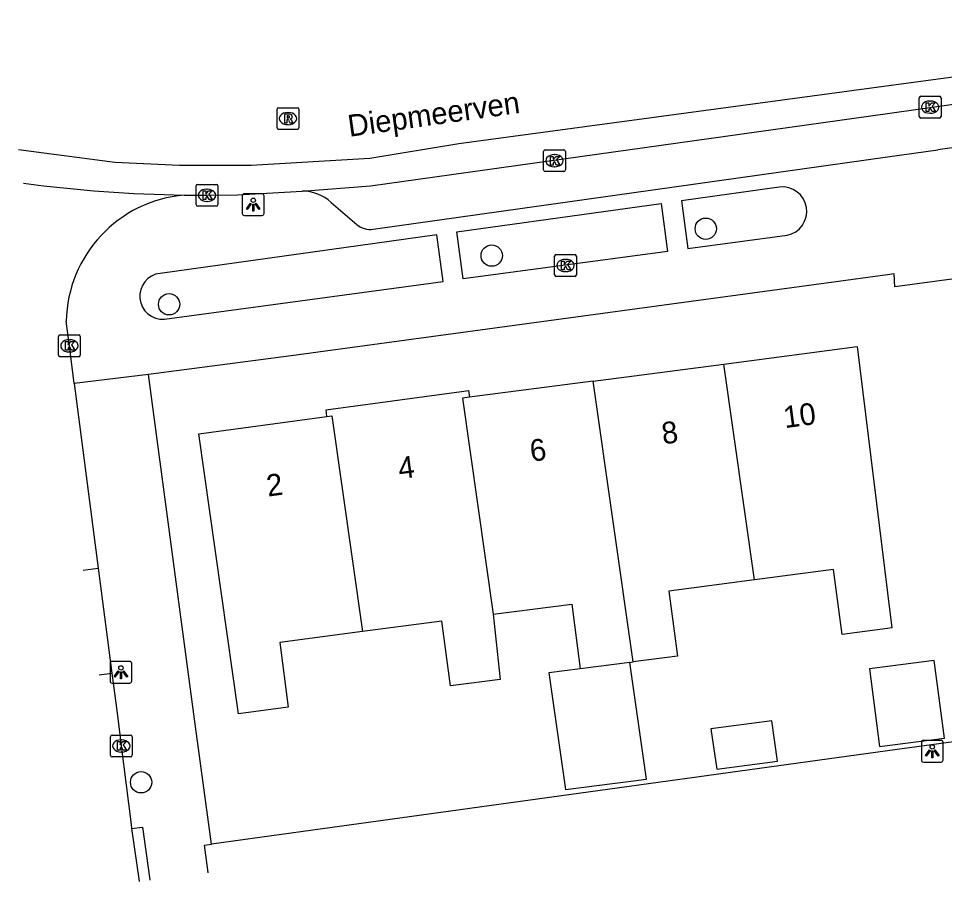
# Model space of a CAD drawing. Extents: x 163427 to 164190, y 380331 to 381641.
# Drawn here: x 163460.1 to 163502.62, y 381492.5 to 381532.13 of the extents above; entities that cross this region are included whole.
import ezdxf

# ---------------------------------------------------------------- set-up
doc = ezdxf.new("R2010")
doc.units = 0
for name, color, linetype in [('IMGEO_Boom', 7, 'Continuous'), ('IMGEO_Kolk', 7, 'Continuous'), ('IMGEO_Lichtpunt', 7, 'Continuous'), ('IMGEO_Openbare_ruimte_label', 7, 'Continuous'), ('IMGEO_Pand', 7, 'Continuous'), ('IMGEO_Pand_nummerreeks', 7, 'Continuous'), ('IMGEO_Rijbaan_lokaal_gesloten', 7, 'Continuous'), ('IMGEO_Rijbaan_lokaal_open', 7, 'Continuous'), ('IMGEO_Rioolput', 7, 'Continuous'), ('IMGEO_Voetpad_open', 7, 'Continuous')]:
    doc.layers.add(name, color=color, linetype=linetype)

msp = doc.modelspace()

# ---------------------------------------------------------------- linework, layer by layer
at = {"layer": 'IMGEO_Boom'}
for centre in [(163491.659, 381522.474), (163481.832, 381521.243), (163467.018, 381519.006), (163465.734, 381497.058)]:
    msp.add_circle(centre, 0.489, dxfattribs=at)
at = {"layer": 'IMGEO_Kolk'}
for p, q in [((163501.46, 381527.633), (163501.46, 381528.485)), ((163501.535, 381528.559), (163502.387, 381528.559)), ((163501.948, 381528.339), (163501.973, 381528.339)), ((163502.461, 381528.485), (163502.461, 381527.633)), ((163501.971, 381527.779), (163501.946, 381527.779)), ((163502.387, 381527.559), (163501.535, 381527.559)), ((163484.288, 381526.099), (163485.14, 381526.099)), ((163484.213, 381525.173), (163484.213, 381526.025)), ((163484.701, 381525.879), (163484.726, 381525.879)), ((163485.214, 381526.025), (163485.214, 381525.173)), ((163484.724, 381525.319), (163484.699, 381525.319)), ((163485.14, 381525.099), (163484.288, 381525.099)), ((163468.257, 381523.586), (163468.257, 381524.438)), ((163468.332, 381524.512), (163469.184, 381524.512)), ((163469.258, 381524.438), (163469.258, 381523.586)), ((163468.745, 381524.292), (163468.77, 381524.292)), ((163468.768, 381523.732), (163468.743, 381523.732)), ((163469.184, 381523.512), (163468.332, 381523.512)), ((163484.72, 381520.36), (163484.72, 381521.212)), ((163484.795, 381521.286), (163485.647, 381521.286)), ((163485.208, 381521.066), (163485.233, 381521.066)), ((163485.721, 381521.212), (163485.721, 381520.36)), ((163485.647, 381520.286), (163484.795, 381520.286)), ((163485.231, 381520.506), (163485.206, 381520.506)), ((163462.014, 381517.6), (163462.866, 381517.6)), ((163461.939, 381516.674), (163461.939, 381517.526)), ((163462.427, 381517.38), (163462.452, 381517.38)), ((163462.94, 381517.526), (163462.94, 381516.674)), ((163462.45, 381516.82), (163462.425, 381516.82)), ((163462.866, 381516.6), (163462.014, 381516.6)), ((163464.322, 381498.301), (163464.322, 381499.153)), ((163464.397, 381499.227), (163465.249, 381499.227)), ((163464.81, 381499.007), (163464.835, 381499.007)), ((163465.323, 381499.153), (163465.323, 381498.301)), ((163464.833, 381498.447), (163464.808, 381498.447)), ((163465.249, 381498.227), (163464.397, 381498.227))]:
    msp.add_line(p, q, dxfattribs=at)
for points in [[(163501.46, 381527.633), (163501.46, 381528.485)], [(163501.535, 381528.559), (163502.387, 381528.559)], [(163501.781, 381528.259), (163501.904, 381528.259), (163501.904, 381528.108), (163502.034, 381528.259), (163502.198, 381528.259), (163502.052, 381528.108), (163502.205, 381527.859), (163502.053, 381527.859), (163501.968, 381528.023), (163501.904, 381527.956), (163501.904, 381527.859), (163501.781, 381527.859), (163501.781, 381528.259)], [(163502.461, 381528.485), (163502.461, 381527.633)], [(163502.387, 381527.559), (163501.535, 381527.559)], [(163484.288, 381526.099), (163485.14, 381526.099)], [(163484.213, 381525.173), (163484.213, 381526.025)], [(163484.534, 381525.799), (163484.657, 381525.799), (163484.657, 381525.648), (163484.787, 381525.799), (163484.951, 381525.799), (163484.805, 381525.648), (163484.958, 381525.399), (163484.806, 381525.399), (163484.721, 381525.563), (163484.657, 381525.496), (163484.657, 381525.399), (163484.534, 381525.399), (163484.534, 381525.799)], [(163485.214, 381526.025), (163485.214, 381525.173)], [(163485.14, 381525.099), (163484.288, 381525.099)], [(163468.257, 381523.586), (163468.257, 381524.438)], [(163468.332, 381524.512), (163469.184, 381524.512)], [(163469.258, 381524.438), (163469.258, 381523.586)], [(163468.578, 381524.212), (163468.701, 381524.212), (163468.701, 381524.061), (163468.831, 381524.212), (163468.995, 381524.212), (163468.849, 381524.061), (163469.002, 381523.812), (163468.85, 381523.812), (163468.765, 381523.976), (163468.701, 381523.909), (163468.701, 381523.812), (163468.578, 381523.812), (163468.578, 381524.212)], [(163469.184, 381523.512), (163468.332, 381523.512)], [(163484.72, 381520.36), (163484.72, 381521.212)], [(163484.795, 381521.286), (163485.647, 381521.286)], [(163485.041, 381520.986), (163485.164, 381520.986), (163485.164, 381520.835), (163485.294, 381520.986), (163485.458, 381520.986), (163485.312, 381520.835), (163485.465, 381520.586), (163485.313, 381520.586), (163485.228, 381520.75), (163485.164, 381520.683), (163485.164, 381520.586), (163485.041, 381520.586), (163485.041, 381520.986)], [(163485.721, 381521.212), (163485.721, 381520.36)], [(163485.647, 381520.286), (163484.795, 381520.286)], [(163462.014, 381517.6), (163462.866, 381517.6)], [(163461.939, 381516.674), (163461.939, 381517.526)], [(163462.26, 381517.3), (163462.383, 381517.3), (163462.383, 381517.149), (163462.513, 381517.3), (163462.677, 381517.3), (163462.531, 381517.149), (163462.684, 381516.9), (163462.532, 381516.9), (163462.447, 381517.064), (163462.383, 381516.997), (163462.383, 381516.9), (163462.26, 381516.9), (163462.26, 381517.3)], [(163462.94, 381517.526), (163462.94, 381516.674)], [(163462.866, 381516.6), (163462.014, 381516.6)], [(163464.322, 381498.301), (163464.322, 381499.153)], [(163464.397, 381499.227), (163465.249, 381499.227)], [(163464.643, 381498.927), (163464.766, 381498.927), (163464.766, 381498.776), (163464.896, 381498.927), (163465.06, 381498.927), (163464.914, 381498.776), (163465.067, 381498.527), (163464.915, 381498.527), (163464.83, 381498.691), (163464.766, 381498.624), (163464.766, 381498.527), (163464.643, 381498.527), (163464.643, 381498.927)], [(163465.323, 381499.153), (163465.323, 381498.301)], [(163465.249, 381498.227), (163464.397, 381498.227)]]:
    msp.add_lwpolyline(points, dxfattribs=at)
for centre, start, end in [((163501.537, 381528.483), 91.552, 178.448), ((163501.537, 381528.483), 91.552, 178.448), ((163502.385, 381528.483), 1.552, 88.448), ((163502.385, 381528.483), 1.552, 88.448), ((163501.537, 381527.635), 181.552, 268.448), ((163501.537, 381527.635), 181.552, 268.448), ((163502.385, 381527.635), 271.552, 358.448), ((163502.385, 381527.635), 271.552, 358.448), ((163484.29, 381526.023), 91.552, 178.448), ((163484.29, 381526.023), 91.552, 178.448), ((163485.138, 381526.023), 1.552, 88.448), ((163485.138, 381526.023), 1.552, 88.448), ((163484.29, 381525.175), 181.552, 268.448), ((163484.29, 381525.175), 181.552, 268.448), ((163485.138, 381525.175), 271.552, 358.448), ((163485.138, 381525.175), 271.552, 358.448), ((163468.334, 381524.436), 91.552, 178.448), ((163468.334, 381524.436), 91.552, 178.448), ((163469.182, 381524.436), 1.552, 88.448), ((163469.182, 381524.436), 1.552, 88.448), ((163468.334, 381523.588), 181.552, 268.448), ((163468.334, 381523.588), 181.552, 268.448), ((163469.182, 381523.588), 271.552, 358.448), ((163469.182, 381523.588), 271.552, 358.448), ((163484.797, 381521.21), 91.552, 178.448), ((163484.797, 381521.21), 91.552, 178.448), ((163485.645, 381521.21), 1.552, 88.448), ((163485.645, 381521.21), 1.552, 88.448), ((163484.797, 381520.362), 181.552, 268.448), ((163484.797, 381520.362), 181.552, 268.448), ((163485.645, 381520.362), 271.552, 358.448), ((163485.645, 381520.362), 271.552, 358.448), ((163462.016, 381517.524), 91.552, 178.448), ((163462.016, 381517.524), 91.552, 178.448), ((163462.864, 381517.524), 1.552, 88.448), ((163462.864, 381517.524), 1.552, 88.448), ((163462.016, 381516.676), 181.552, 268.448), ((163462.016, 381516.676), 181.552, 268.448), ((163462.864, 381516.676), 271.552, 358.448), ((163462.864, 381516.676), 271.552, 358.448), ((163464.399, 381499.151), 91.552, 178.448), ((163464.399, 381499.151), 91.552, 178.448), ((163465.247, 381499.151), 1.552, 88.448), ((163465.247, 381499.151), 1.552, 88.448), ((163464.399, 381498.303), 181.552, 268.448), ((163464.399, 381498.303), 181.552, 268.448), ((163465.247, 381498.303), 271.552, 358.448), ((163465.247, 381498.303), 271.552, 358.448)]:
    msp.add_arc(centre, 0.0765, start, end, dxfattribs=at)
for centre, major_axis, ratio, start_param, end_param in [((163501.947, 381528.059), (-0.387, 0.002), 0.722429, 4.712389, 7.853982), ((163501.972, 381528.059), (-0.39, 0.002), 0.717154, 1.570796, 4.712389), ((163484.7, 381525.599), (-0.387, 0.002), 0.722429, 4.712389, 7.853982), ((163484.725, 381525.599), (-0.39, 0.002), 0.717154, 1.570796, 4.712389), ((163468.744, 381524.012), (-0.387, 0.002), 0.722429, 4.712389, 7.853982), ((163468.769, 381524.012), (-0.39, 0.002), 0.717154, 1.570796, 4.712389), ((163485.207, 381520.786), (-0.387, 0.002), 0.722429, 4.712389, 7.853982), ((163485.232, 381520.786), (-0.39, 0.002), 0.717154, 1.570796, 4.712389), ((163462.426, 381517.1), (-0.387, 0.002), 0.722429, 4.712389, 7.853982), ((163462.451, 381517.1), (-0.39, 0.002), 0.717154, 1.570796, 4.712389), ((163464.809, 381498.727), (-0.387, 0.002), 0.722429, 4.712389, 7.853982), ((163464.834, 381498.727), (-0.39, 0.002), 0.717154, 1.570796, 4.712389)]:
    msp.add_ellipse(centre, major_axis=major_axis, ratio=ratio, start_param=start_param, end_param=end_param, dxfattribs=at)
at = {"layer": 'IMGEO_Lichtpunt'}
for p, q in [((163470.38, 381523.987), (163470.38, 381523.18)), ((163470.38, 381523.987), (163470.38, 381523.18)), ((163471.282, 381524.082), (163470.474, 381524.082)), ((163471.282, 381524.082), (163470.474, 381524.082)), ((163471.376, 381523.18), (163471.376, 381523.987)), ((163471.376, 381523.18), (163471.376, 381523.987)), ((163470.474, 381523.086), (163471.282, 381523.086)), ((163470.474, 381523.086), (163471.282, 381523.086)), ((163464.306, 381502.515), (163464.306, 381501.708)), ((163464.306, 381502.515), (163464.306, 381501.708)), ((163465.208, 381502.61), (163464.4, 381502.61)), ((163465.208, 381502.61), (163464.4, 381502.61)), ((163465.302, 381501.708), (163465.302, 381502.515)), ((163465.302, 381501.708), (163465.302, 381502.515)), ((163464.4, 381501.614), (163465.208, 381501.614)), ((163464.4, 381501.614), (163465.208, 381501.614)), ((163501.56, 381498.888), (163501.56, 381498.081)), ((163501.56, 381498.888), (163501.56, 381498.081)), ((163502.462, 381498.983), (163501.654, 381498.983)), ((163502.462, 381498.983), (163501.654, 381498.983)), ((163502.556, 381498.081), (163502.556, 381498.888)), ((163502.556, 381498.081), (163502.556, 381498.888)), ((163501.654, 381497.987), (163502.462, 381497.987)), ((163501.654, 381497.987), (163502.462, 381497.987))]:
    msp.add_line(p, q, dxfattribs=at)
for points in [[(163470.754, 381523.651), (163470.793, 381523.623), (163470.605, 381523.361), (163470.567, 381523.388), (163470.754, 381523.651)], [(163470.856, 381523.603), (163470.903, 381523.603), (163470.903, 381523.281), (163470.856, 381523.281), (163470.856, 381523.603)], [(163470.966, 381523.623), (163471.004, 381523.65), (163471.191, 381523.388), (163471.152, 381523.36), (163470.966, 381523.623)], [(163464.68, 381502.179), (163464.719, 381502.151), (163464.531, 381501.889), (163464.493, 381501.916), (163464.68, 381502.179)], [(163464.782, 381502.131), (163464.829, 381502.131), (163464.829, 381501.809), (163464.782, 381501.809), (163464.782, 381502.131)], [(163464.892, 381502.151), (163464.93, 381502.178), (163465.117, 381501.916), (163465.078, 381501.888), (163464.892, 381502.151)], [(163501.934, 381498.552), (163501.973, 381498.524), (163501.785, 381498.262), (163501.747, 381498.289), (163501.934, 381498.552)], [(163502.036, 381498.504), (163502.083, 381498.504), (163502.083, 381498.182), (163502.036, 381498.182), (163502.036, 381498.504)], [(163502.146, 381498.524), (163502.184, 381498.551), (163502.371, 381498.289), (163502.332, 381498.261), (163502.146, 381498.524)]]:
    msp.add_lwpolyline(points, dxfattribs=at)
for centre in [(163470.879, 381523.785), (163464.805, 381502.313), (163502.059, 381498.686)]:
    msp.add_circle(centre, 0.0994, dxfattribs=at)
for centre, start, end in [((163470.474, 381523.987), 90, 180), ((163470.474, 381523.987), 90, 180), ((163471.282, 381523.987), 0, 90), ((163471.282, 381523.987), 0, 90), ((163470.474, 381523.18), 180, 270), ((163470.474, 381523.18), 180, 270), ((163471.282, 381523.18), 270, 0), ((163471.282, 381523.18), 270, 360), ((163464.4, 381502.515), 90, 180), ((163464.4, 381502.515), 90, 180), ((163465.208, 381502.515), 0, 90), ((163465.208, 381502.515), 0, 90), ((163464.4, 381501.708), 180, 270), ((163464.4, 381501.708), 180, 270), ((163465.208, 381501.708), 270, 0), ((163465.208, 381501.708), 270, 360), ((163501.654, 381498.888), 90, 180), ((163501.654, 381498.888), 90, 180), ((163502.462, 381498.888), 0, 90), ((163502.462, 381498.888), 0, 90), ((163501.654, 381498.081), 180, 270), ((163501.654, 381498.081), 180, 270), ((163502.462, 381498.081), 270, 0), ((163502.462, 381498.081), 270, 360)]:
    msp.add_arc(centre, 0.0946, start, end, dxfattribs=at)
at = {"layer": 'IMGEO_Pand'}
for points in [[(163492.491, 381516.264), (163498.608, 381517.064), (163500, 381505.754), (163500.198, 381504.145), (163500, 381504.119), (163497.915, 381503.845), (163497.524, 381506.824), (163493.902, 381506.348)], [(163486.49, 381515.479), (163492.491, 381516.264)], [(163493.902, 381506.348), (163492.491, 381516.264)], [(163486.49, 381515.479), (163480.809, 381514.736)], [(163488.326, 381502.585), (163486.49, 381515.479)], [(163474.267, 381513.847), (163474.226, 381514.154), (163474.449, 381514.184), (163480.445, 381514.999), (163480.767, 381515.043), (163480.809, 381514.736)], [(163480.809, 381514.736), (163480.488, 381514.694), (163481.901, 381504.771)], [(163475.9, 381503.983), (163472.096, 381503.483), (163472.489, 381500.505), (163470.206, 381500.205), (163468.376, 381513.061), (163474.267, 381513.847)], [(163474.267, 381513.847), (163474.493, 381513.877), (163475.9, 381503.983)], [(163493.902, 381506.348), (163489.97, 381505.831), (163490.362, 381502.853), (163488.326, 381502.585)], [(163481.901, 381504.771), (163485.504, 381505.245), (163485.897, 381502.266)], [(163481.901, 381504.771), (163482.225, 381501.784), (163479.932, 381501.483), (163479.541, 381504.462), (163475.9, 381503.983)], [(163485.897, 381502.266), (163484.454, 381502.078), (163485.217, 381496.721), (163488.939, 381497.209), (163488.175, 381502.565)], [(163488.175, 381502.565), (163485.897, 381502.266)], [(163488.175, 381502.565), (163488.326, 381502.585)], [(163499.175, 381502.264), (163499.643, 381498.698), (163502.616, 381499.088), (163502.148, 381502.655), (163499.175, 381502.264)], [(163491.898, 381499.518), (163492.162, 381497.669), (163494.951, 381498.035), (163494.687, 381499.884), (163491.898, 381499.518)]]:
    msp.add_lwpolyline(points, dxfattribs=at)
at = {"layer": 'IMGEO_Rijbaan_lokaal_gesloten'}
for points in [[(163528.01, 381532.127), (163525.359, 381531.987), (163517.306, 381531.367), (163499.836, 381529.012), (163480.321, 381526.377), (163476.232, 381525.695), (163470.78, 381525.385), (163467.492, 381525.377), (163464.523, 381525.509), (163460.104, 381526.095)], [(163473.128, 381524.207), (163476.271, 381524.451), (163500, 381527.771), (163507.794, 381528.862)], [(163467.712, 381524.019), (163468.757, 381524.014), (163470.153, 381524.029), (163473.128, 381524.207)]]:
    msp.add_lwpolyline(points, dxfattribs=at)
msp.add_arc((163468.685, 381587.432), 63.42, 262.43797, 269.12099, dxfattribs=at)
at = {"layer": 'IMGEO_Rijbaan_lokaal_open'}
for points in [[(163462.663, 381515.373), (163462.438, 381517.1), (163462.296, 381518.23)], [(163462.663, 381515.373), (163463.766, 381506.886)], [(163463.069, 381506.793), (163463.766, 381506.886)], [(163463.766, 381506.886), (163464.393, 381502.068)], [(163463.807, 381501.989), (163464.393, 381502.068)], [(163464.393, 381502.068), (163464.658, 381500), (163464.822, 381498.726), (163465.271, 381495.12), (163465.298, 381494.93)], [(163513.136, 381500.288), (163511.008, 381500), (163500, 381498.51), (163468.966, 381494.225)], [(163465.298, 381494.93), (163465.642, 381492.516), (163465.644, 381492.505)], [(163468.816, 381492.902), (163468.815, 381492.913), (163468.645, 381494.168), (163468.966, 381494.225)]]:
    msp.add_lwpolyline(points, dxfattribs=at)
msp.add_arc((163468.213, 381518.122), 5.918, 94.8544, 178.9588, dxfattribs=at)
at = {"layer": 'IMGEO_Rioolput'}
for p, q in [((163471.978, 381527.107), (163471.978, 381527.959)), ((163472.053, 381528.033), (163472.905, 381528.033)), ((163472.466, 381527.813), (163472.491, 381527.813)), ((163472.979, 381527.959), (163472.979, 381527.107)), ((163472.905, 381527.033), (163472.053, 381527.033)), ((163472.489, 381527.253), (163472.464, 381527.253))]:
    msp.add_line(p, q, dxfattribs=at)
for points in [[(163471.978, 381527.107), (163471.978, 381527.959)], [(163472.053, 381528.033), (163472.905, 381528.033)], [(163472.979, 381527.959), (163472.979, 381527.107)], [(163472.567, 381527.731), (163472.315, 381527.733), (163472.315, 381527.333)], [(163472.315, 381527.333), (163472.439, 381527.333), (163472.439, 381527.495), (163472.45, 381527.495)], [(163472.493, 381527.652), (163472.439, 381527.652), (163472.439, 381527.571)], [(163472.439, 381527.571), (163472.491, 381527.571)], [(163472.497, 381527.466), (163472.568, 381527.333), (163472.708, 381527.333), (163472.643, 381527.459)], [(163472.905, 381527.033), (163472.053, 381527.033)]]:
    msp.add_lwpolyline(points, dxfattribs=at)
for centre, radius, start, end in [((163472.055, 381527.957), 0.0765, 91.552, 178.448), ((163472.055, 381527.957), 0.0765, 91.552, 178.448), ((163472.903, 381527.957), 0.0765, 1.552, 88.448), ((163472.903, 381527.957), 0.0765, 1.552, 88.448), ((163472.449, 381527.442), 0.0533, 26.0293, 88.6989), ((163472.475, 381527.76), 0.19, 274.7715, 282.9687), ((163472.499, 381527.556), 0.0964, 77.0061, 93.1865), ((163472.513, 381527.613), 0.0378, 276.6634, 79.6772), ((163472.566, 381527.621), 0.109, 350.3612, 89.416), ((163472.564, 381527.621), 0.112, 277.5842, 350.9817), ((163472.548, 381527.406), 0.108, 29.5134, 73.7905), ((163472.055, 381527.109), 0.0765, 181.552, 268.448), ((163472.055, 381527.109), 0.0765, 181.552, 268.448), ((163472.903, 381527.109), 0.0765, 271.552, 358.448), ((163472.903, 381527.109), 0.0765, 271.552, 358.448)]:
    msp.add_arc(centre, radius, start, end, dxfattribs=at)
for centre, major_axis, ratio, start_param, end_param in [((163472.465, 381527.533), (-0.387, 0.002), 0.722429, 4.712389, 7.853982), ((163472.49, 381527.533), (-0.39, 0.002), 0.717154, 1.570796, 4.712389)]:
    msp.add_ellipse(centre, major_axis=major_axis, ratio=ratio, start_param=start_param, end_param=end_param, dxfattribs=at)
at = {"layer": 'IMGEO_Voetpad_open'}
for points in [[(163476.384, 381522.451), (163500, 381525.772), (163502.318, 381526.098)], [(163495.035, 381524.388), (163490.538, 381523.761), (163490.838, 381521.562), (163495.39, 381522.175)], [(163532.089, 381524.073), (163500.343, 381519.8), (163500.304, 381520.404), (163500, 381520.363), (163472.627, 381516.638), (163466.066, 381515.775)], [(163474.465, 381523.686), (163475.63, 381522.674)], [(163480.525, 381520.172), (163480.235, 381522.326), (163489.608, 381523.631), (163489.907, 381521.436), (163480.525, 381520.172)], [(163466.806, 381518.325), (163479.603, 381520.049), (163479.314, 381522.197), (163466.602, 381520.427)], [(163466.066, 381515.775), (163462.663, 381515.373)], [(163468.966, 381494.225), (163468.184, 381499.951), (163466.066, 381515.775)], [(163465.298, 381494.93), (163465.794, 381494.998), (163466.138, 381492.578), (163466.14, 381492.567)]]:
    msp.add_lwpolyline(points, dxfattribs=at)
for centre, radius, start, end in [((163550.032, 381187.984), 341.464, 94.50299, 98.03238), ((163495.175, 381523.275), 1.121, 281.0623, 97.1647), ((163473.078, 381522.102), 2.106, 48.7886, 88.6318), ((163476.253, 381523.394), 0.952, 229.1353, 277.9129), ((163466.723, 381519.378), 1.056, 96.5893, 274.4972)]:
    msp.add_arc(centre, radius, start, end, dxfattribs=at)

# ---------------------------------------------------------------- texts
at = {"layer": 'IMGEO_Openbare_ruimte_label'}
msp.add_text('Diepmeerven', height=1, rotation=7.9923, dxfattribs=at).set_placement((163475.296, 381526.693))
at = {"layer": 'IMGEO_Pand_nummerreeks'}
for s, rotation, p in [('10', 7.5426, (163495.289, 381513.316)), ('8', 7.5426, (163489.7, 381512.575)), ('6', 7.5401, (163483.649, 381511.776)), ('4', 7.5401, (163477.602, 381510.975)), ('2', 7.5401, (163471.554, 381510.174))]:
    msp.add_text(s, height=1, rotation=rotation, dxfattribs=at).set_placement(p)

doc.saveas('drawing.dxf')
